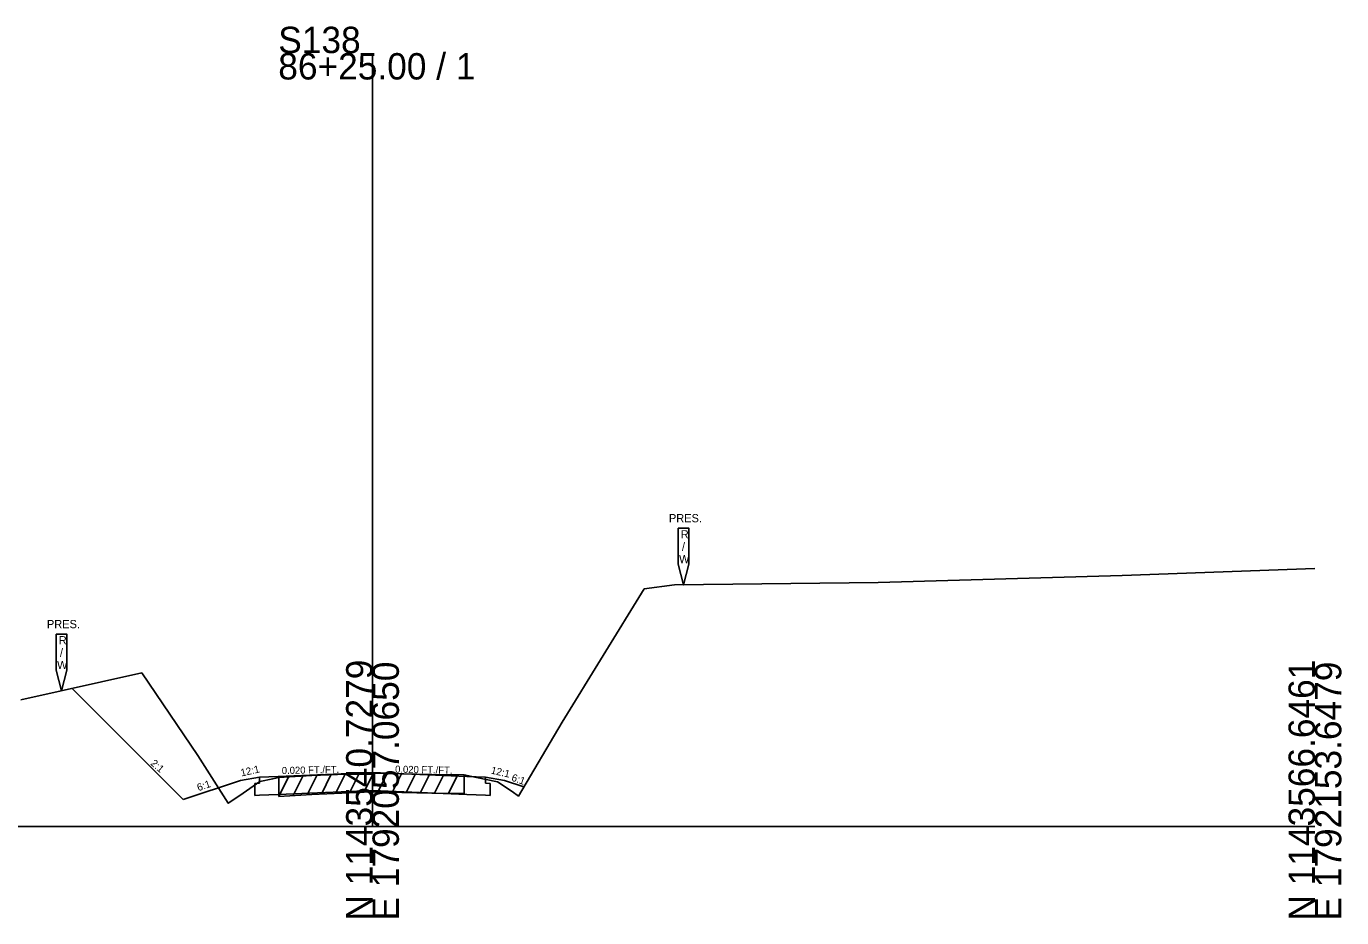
# Model space of a CAD drawing. Extents: x -26 to 1203, y -10 to 19606.
# Drawn here: x 63.3 to 202.8, y 12490.3 to 12584.9 of the extents above; entities that cross this region are included whole.
import ezdxf

# ---------------------------------------------------------------- set-up
doc = ezdxf.new("R2010")
doc.units = 0
for name, color, linetype in [('RD_EX_Driveway', 7, 'Continuous'), ('RD_GPK_XS_Cell', 7, 'Continuous'), ('RD_XS_Base', 7, 'Continuous'), ('RD_XS_EarthShd', 7, 'Continuous'), ('RD_XS_ExGround', 7, 'Continuous'), ('RD_XS_ExPaveRet', 7, 'Continuous'), ('RD_XS_ExRW', 7, 'Continuous'), ('RD_XS_Pave', 7, 'Continuous'), ('RD_XS_TX_Slope', 7, 'Continuous')]:
    doc.layers.add(name, color=color, linetype=linetype)

msp = doc.modelspace()

# ---------------------------------------------------------------- linework, layer by layer
at = {"layer": 'RD_GPK_XS_Cell'}
for p, q in [((100, 12500), (100, 12582.06)), ((0, 12500), (100, 12500)), ((100, 12500), (200, 12500))]:
    msp.add_line(p, q, dxfattribs=at)
at = {"layer": 'RD_XS_Base'}
for p, q in [((88, 12504.58), (87.5, 12504.56)), ((87.5, 12503.29), (87.5, 12504.56)), ((88, 12504.58), (88, 12505.21)), ((112, 12504.58), (112, 12505.21)), ((112, 12504.58), (112.5, 12504.56)), ((112.5, 12503.29), (112.5, 12504.56)), ((88, 12503.31), (87.5, 12503.29)), ((88, 12503.31), (90, 12503.39)), ((90, 12503.39), (100, 12503.81)), ((110, 12503.39), (100, 12503.81)), ((112, 12503.31), (110, 12503.39)), ((112, 12503.31), (112.5, 12503.29))]:
    msp.add_line(p, q, dxfattribs=at)
at = {"layer": 'RD_XS_EarthShd'}
for p, q in [((79.92, 12502.85), (68.13, 12514.64)), ((86, 12504.88), (79.92, 12502.85)), ((88, 12505.21), (86, 12504.88)), ((88, 12505.21), (86, 12504.88)), ((112, 12505.21), (114, 12504.88)), ((112, 12505.21), (114, 12504.88)), ((114, 12504.88), (116.07, 12504.19))]:
    msp.add_line(p, q, dxfattribs=at)
at = {"layer": 'RD_XS_ExGround'}
msp.add_lwpolyline([(62.68, 12513.42), (75.52, 12516.29), (81.45, 12507.53), (84.69, 12502.46), (85.92, 12503.29), (88.03, 12504.77), (89.41, 12505.05), (90.07, 12505.18), (93.55, 12505.38), (99.94, 12505.66), (106.29, 12505.52), (109.71, 12505.48), (111.04, 12505.19), (113.26, 12504.74), (114.81, 12503.7), (115.49, 12503.21), (120.13, 12511.07), (128.84, 12525.2), (132.05, 12525.62), (153.65, 12525.89), (179.54, 12526.62), (200, 12527.35)], dxfattribs=at)
at = {"layer": 'RD_XS_ExPaveRet'}
for p, q in [((90.07, 12503.18), (91.1, 12505.24)), ((90.07, 12503.18), (90.07, 12505.18)), ((91.57, 12503.27), (92.6, 12505.33)), ((93.07, 12503.35), (94.1, 12505.41)), ((94.57, 12503.43), (95.59, 12505.47)), ((96.07, 12503.49), (97.09, 12505.54)), ((97.57, 12503.56), (98.59, 12505.6)), ((99.07, 12503.62), (100.09, 12505.66)), ((100.57, 12503.65), (101.56, 12505.62)), ((102.07, 12503.61), (103.06, 12505.59)), ((103.57, 12503.58), (104.56, 12505.56)), ((105.07, 12503.54), (106.06, 12505.52)), ((106.57, 12503.51), (107.56, 12505.5)), ((108.07, 12503.5), (109.06, 12505.49)), ((109.71, 12505.48), (109.71, 12503.48)), ((90.07, 12503.18), (93.55, 12503.38)), ((93.55, 12503.38), (99.94, 12503.66)), ((99.94, 12503.66), (106.29, 12503.52)), ((106.29, 12503.52), (109.71, 12503.48))]:
    msp.add_line(p, q, dxfattribs=at)
at = {"layer": 'RD_XS_ExRW'}
for points in [[(132.45, 12531.65), (133.55, 12531.65), (133.55, 12527.82), (133, 12525.63), (132.45, 12527.82)], [(66.45, 12520.4), (67.55, 12520.4), (67.55, 12516.58), (67, 12514.39), (66.45, 12516.58)]]:
    msp.add_lwpolyline(points, close=True, dxfattribs=at)
at = {"layer": 'RD_XS_Pave'}
for p, q in [((88, 12505.21), (90, 12505.3)), ((90, 12505.3), (100, 12505.71)), ((110, 12505.3), (100, 12505.71)), ((112, 12505.21), (110, 12505.3))]:
    msp.add_line(p, q, dxfattribs=at)

# ---------------------------------------------------------------- texts
at = {"layer": 'RD_EX_Driveway'}
msp.add_text('542.83', height=0.0975, rotation=90, dxfattribs=at).set_placement((100.1, 12505.66))
at = {"layer": 'RD_GPK_XS_Cell'}
for s, p in [('S138', (90, 12582.06)), ('86+25.00 / 1', (90, 12579.26))]:
    msp.add_text(s, height=2.8, dxfattribs=at).set_placement(p)
for s, p in [('N 1143540.7279', (100, 12490)), ('E 1792057.0650', (102.8, 12490)), ('N 1143566.6461', (200, 12490)), ('E 1792153.6479', (202.8, 12490))]:
    msp.add_text(s, height=2.8, rotation=90, dxfattribs=at).set_placement(p)
at = {"layer": 'RD_XS_ExRW'}
for s, p in [('PRES.', (131.45, 12532.27)), ('R', (132.71, 12530.55)), ('/', (132.83, 12529.24)), ('W', (132.53, 12527.93)), ('PRES.', (65.45, 12521.03)), ('R', (66.71, 12519.31)), ('/', (66.83, 12518)), ('W', (66.53, 12516.69))]:
    msp.add_text(s, height=0.875, dxfattribs=at).set_placement(p)
at = {"layer": 'RD_XS_TX_Slope'}
for s, height, rotation, p in [('2:1', 0.778, 319.3411, (76.38, 12506.59)), ('12:1', 0.778, 12.7511, (86.1, 12505.29)), ('12:1', 0.778, 12.7511, (86.1, 12505.29)), ('0.020 FT./FT.', 0.7518, 1.1916, (90.38, 12505.55)), ('0.020 FT./FT.', 0.7518, 358.8084, (102.39, 12505.7)), ('12:1', 0.778, 347.2489, (112.51, 12505.61)), ('6:1', 0.778, 19.3982, (81.54, 12503.72)), ('6:1', 0.778, 340.6018, (114.68, 12504.87))]:
    msp.add_text(s, height=height, rotation=rotation, dxfattribs=at).set_placement(p)

doc.saveas('drawing.dxf')
